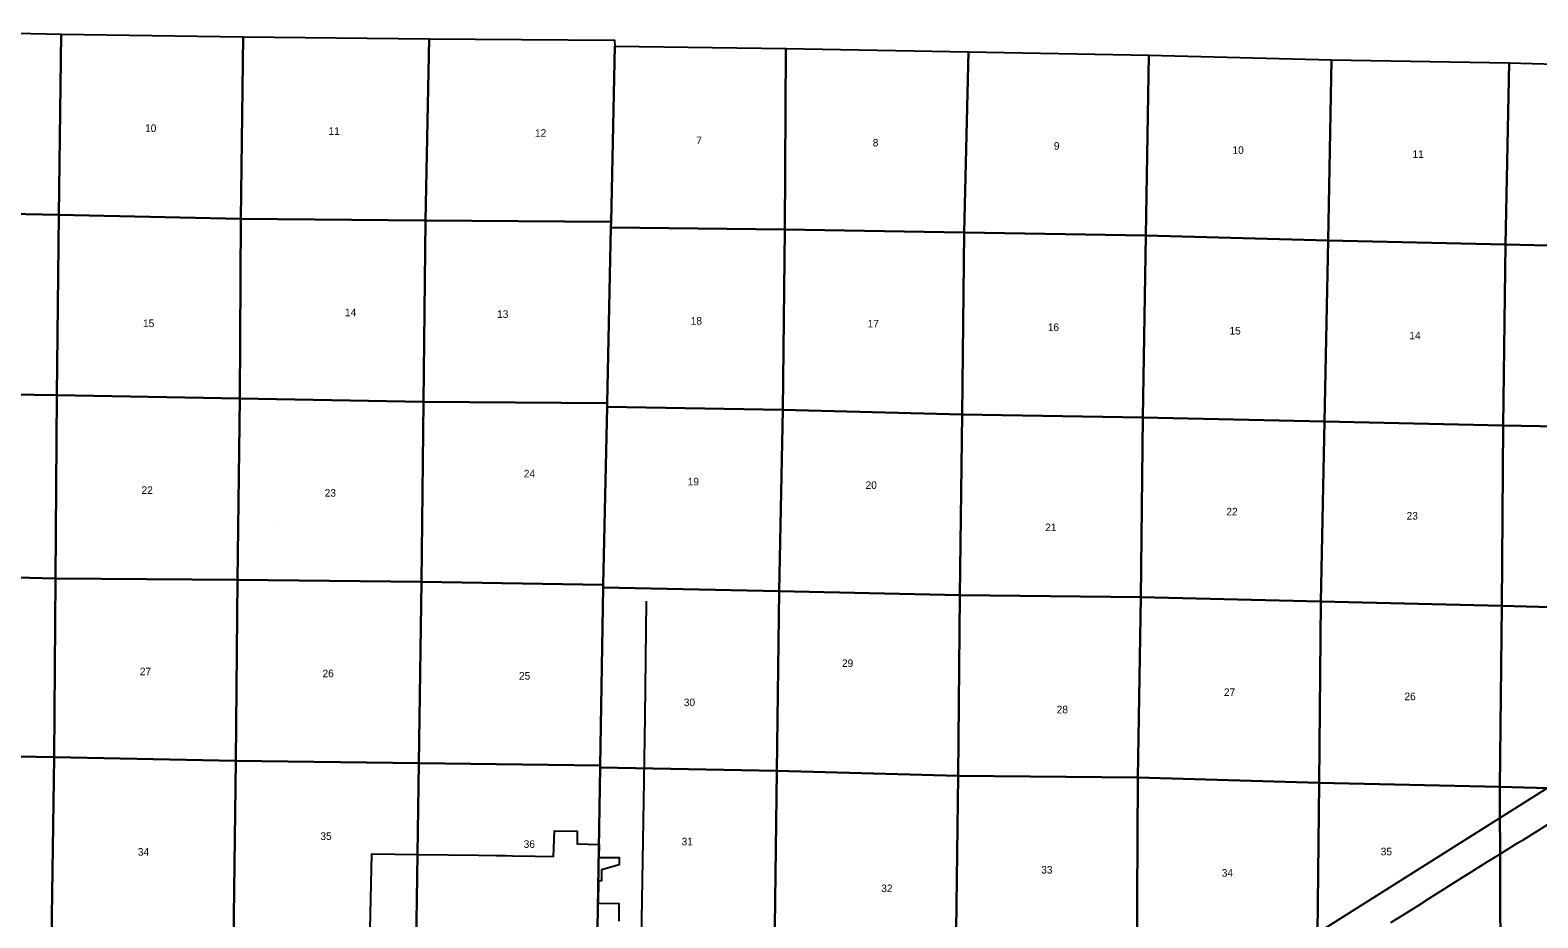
# Model space of a CAD drawing. Extents: x 1587405 to 1714697, y 1028970 to 1155083.
# Drawn here: x 1634826 to 1678758, y 1125096 to 1150963 of the extents above; entities that cross this region are included whole.
import ezdxf

# ---------------------------------------------------------------- set-up
doc = ezdxf.new("R2010")
doc.units = 0
for name, color, linetype in [('GM_X_Airport_Location_Class_3', 7, 'Continuous'), ('GM_X_Corporation', 7, 'Continuous'), ('GM_X_Interstate_Location', 7, 'Continuous'), ('GM_X_Rail_Line', 7, 'Continuous'), ('GM_X_Section', 7, 'Continuous'), ('GM_X_Section_Text', 7, 'Continuous'), ('GM_X_State_Location', 7, 'Continuous'), ('GM_X_State_Route', 7, 'Continuous'), ('GM_X_Unincorporated_Location', 7, 'Continuous')]:
    doc.layers.add(name, color=color, linetype=linetype)

msp = doc.modelspace()

# ---------------------------------------------------------------- linework, layer by layer
at = {"layer": 'GM_X_Airport_Location_Class_3'}
msp.add_line((1642071, 1136494), (1642071, 1136494), dxfattribs=at)
at = {"layer": 'GM_X_Corporation'}
msp.add_lwpolyline([(1644727, 1124331), (1644784, 1126962), (1646120, 1126944), (1647895, 1126921), (1648410, 1126912), (1648607, 1126910), (1648684, 1126908), (1648878, 1126905), (1649544, 1126894), (1650077, 1126886), (1650104, 1127635), (1650768, 1127623), (1650764, 1127251), (1651405, 1127232), (1651400, 1126856), (1651993, 1126850), (1651990, 1126644), (1651472, 1126496), (1651472, 1126171), (1651391, 1126171), (1651382, 1125527), (1651977, 1125511), (1651980, 1124997)], dxfattribs=at)
at = {"layer": 'GM_X_Rail_Line'}
for points in [[(1653568, 1112819), (1655300, 1113913), (1659870, 1116798), (1669731, 1123017), (1672359, 1124671), (1681695, 1130554), (1684437, 1132280), (1688527, 1134851), (1688807, 1135025), (1688953, 1135113), (1689087, 1135186), (1689268, 1135279), (1689470, 1135381), (1689588, 1135442), (1689734, 1135522), (1689884, 1135608), (1690363, 1135905), (1690749, 1136148), (1691070, 1136368)], [(1652548, 1112174), (1652519, 1112269), (1652498, 1112347), (1652484, 1112418), (1652474, 1112488), (1652466, 1112571), (1652461, 1112684), (1652464, 1112911), (1652505, 1115461), (1652527, 1116927), (1652548, 1118268), (1652590, 1120952), (1652612, 1122400), (1652653, 1125050), (1652715, 1129083), (1652745, 1130967), (1652787, 1134323)]]:
    msp.add_lwpolyline(points, dxfattribs=at)
at = {"layer": 'GM_X_Section'}
for points in [[(1630433, 1150963), (1635733, 1150849), (1635661, 1145583), (1630372, 1145688)], [(1635733, 1150849), (1641031, 1150772), (1640961, 1145469), (1635661, 1145583)], [(1641031, 1150772), (1646452, 1150709), (1646346, 1145412), (1640961, 1145469)], [(1646452, 1150709), (1651857, 1150670), (1651861, 1150497), (1651755, 1145373), (1646346, 1145412)], [(1651861, 1150497), (1656847, 1150430), (1656816, 1145157), (1651747, 1145211), (1651755, 1145373)], [(1656847, 1150430), (1662164, 1150328), (1662038, 1145064), (1656816, 1145157)], [(1662164, 1150328), (1667424, 1150230), (1667334, 1144976), (1662038, 1145064)], [(1667424, 1150230), (1672742, 1150098), (1672650, 1144837), (1667334, 1144976)], [(1672742, 1150098), (1677925, 1150009), (1677820, 1144716), (1672650, 1144837)], [(1677925, 1150009), (1683291, 1149852), (1683213, 1144589), (1677820, 1144716)], [(1630372, 1145688), (1635661, 1145583), (1635601, 1140326), (1630302, 1140403)], [(1635661, 1145583), (1640961, 1145469), (1640933, 1140234), (1635601, 1140326)], [(1640961, 1145469), (1646346, 1145412), (1646287, 1140136), (1640933, 1140234)], [(1646346, 1145412), (1651755, 1145373), (1651747, 1145211), (1651642, 1140090), (1646287, 1140136)], [(1651747, 1145211), (1656816, 1145157), (1656763, 1139895), (1651642, 1139982), (1651642, 1140090)], [(1662038, 1145064), (1661982, 1139762), (1656763, 1139895), (1656816, 1145157)], [(1667334, 1144976), (1667248, 1139679), (1661982, 1139762), (1662038, 1145064)], [(1672650, 1144837), (1672545, 1139561), (1667248, 1139679), (1667334, 1144976)], [(1677820, 1144716), (1677747, 1139442), (1672545, 1139561), (1672650, 1144837)], [(1683213, 1144589), (1683123, 1139347), (1677747, 1139442), (1677820, 1144716)], [(1630302, 1140403), (1635601, 1140326), (1635561, 1134983), (1630259, 1135120)], [(1635601, 1140326), (1640933, 1140234), (1640872, 1134949), (1635561, 1134983)], [(1640933, 1140234), (1646287, 1140136), (1646226, 1134889), (1640872, 1134949)], [(1646287, 1140136), (1651642, 1140090), (1651642, 1139982), (1651525, 1134804), (1646226, 1134889)], [(1651642, 1139982), (1656763, 1139895), (1656654, 1134619), (1651524, 1134718), (1651525, 1134804)], [(1656763, 1139895), (1661982, 1139762), (1661911, 1134500), (1656654, 1134619)], [(1661982, 1139762), (1667248, 1139679), (1667189, 1134440), (1661911, 1134500)], [(1667248, 1139679), (1672545, 1139561), (1672435, 1134317), (1667189, 1134440)], [(1672545, 1139561), (1677747, 1139442), (1677705, 1134187), (1672435, 1134317)], [(1677747, 1139442), (1683123, 1139347), (1683127, 1139277), (1683047, 1134044), (1677705, 1134187)], [(1635561, 1134983), (1635521, 1129774), (1630217, 1129877), (1630259, 1135120)], [(1640872, 1134949), (1640821, 1129675), (1635521, 1129774), (1635561, 1134983)], [(1646226, 1134889), (1646147, 1129603), (1640821, 1129675), (1640872, 1134949)], [(1651525, 1134804), (1651524, 1134718), (1651432, 1129536), (1646147, 1129603), (1646226, 1134889)], [(1656654, 1134619), (1656587, 1129382), (1651431, 1129478), (1651432, 1129536), (1651524, 1134718)], [(1656654, 1134619), (1661911, 1134500), (1661871, 1129233), (1656587, 1129382)], [(1661911, 1134500), (1667189, 1134440), (1667104, 1129185), (1661871, 1129233)], [(1667189, 1134440), (1672435, 1134317), (1672391, 1129030), (1667104, 1129185)], [(1672435, 1134317), (1677705, 1134187), (1677648, 1128918), (1672391, 1129030)], [(1677705, 1134187), (1683047, 1134044), (1683047, 1133992), (1682995, 1128763), (1677648, 1128918)], [(1630217, 1129877), (1635521, 1129774), (1635452, 1124488), (1635336, 1124489), (1630175, 1124565)], [(1635521, 1129774), (1640821, 1129675), (1640754, 1124394), (1635452, 1124488)], [(1640821, 1129675), (1646147, 1129603), (1646074, 1124319), (1646050, 1124319), (1640754, 1124394)], [(1646147, 1129603), (1651432, 1129536), (1651431, 1129478), (1651350, 1124201), (1646074, 1124319)], [(1651431, 1129478), (1656587, 1129382), (1656514, 1124092), (1656340, 1124096), (1651350, 1124201)], [(1656587, 1129382), (1661871, 1129233), (1661797, 1123966), (1656514, 1124092)], [(1661871, 1129233), (1667104, 1129185), (1667070, 1123870), (1661837, 1123968), (1661797, 1123966)], [(1667104, 1129185), (1672391, 1129030), (1672328, 1123761), (1667070, 1123870)], [(1672391, 1129030), (1677648, 1128918), (1677670, 1123620), (1672404, 1123756), (1672328, 1123761)], [(1677648, 1128918), (1682995, 1128763), (1682911, 1123475), (1677670, 1123620)]]:
    msp.add_lwpolyline(points, close=True, dxfattribs=at)
at = {"layer": 'GM_X_State_Route'}
msp.add_lwpolyline([(1674479, 1124959), (1674826, 1125178), (1675286, 1125466), (1675576, 1125651), (1676520, 1126248), (1676728, 1126379), (1677286, 1126725), (1677523, 1126872), (1677649, 1126950), (1678176, 1127277), (1678346, 1127383), (1679713, 1128231)], dxfattribs=at)
at = {"layer": 'GM_X_Unincorporated_Location'}
msp.add_line((1651584, 1134718), (1651584, 1134718), dxfattribs=at)

# ---------------------------------------------------------------- texts
at = {"layer": 'GM_X_Interstate_Location'}
for s in ['.', '-', ',']:
    msp.add_text(s, height=1, dxfattribs=at).set_placement((1648860, 1137098))
msp.add_text('75', height=1, rotation=0, dxfattribs=at).set_placement((1648656, 1136891))
at = {"layer": 'GM_X_Section_Text'}
for s, p in [('10', (1638175, 1147995)), ('11', (1643523, 1147912)), ('12', (1649536, 1147856)), ('7', (1654237, 1147641)), ('8', (1659378, 1147573)), ('9', (1664656, 1147480)), ('10', (1669861, 1147359)), ('11', (1675106, 1147238)), ('14', (1644000, 1142627)), ('13', (1648431, 1142579)), ('15', (1638115, 1142311)), ('18', (1654074, 1142381)), ('17', (1659229, 1142300)), ('16', (1664478, 1142196)), ('15', (1669771, 1142093)), ('14', (1675014, 1141956)), ('24', (1649210, 1137930)), ('19', (1653986, 1137697)), ('22', (1638071, 1137450)), ('23', (1643409, 1137369)), ('20', (1659169, 1137596)), ('22', (1669681, 1136821)), ('21', (1664403, 1136365)), ('23', (1674935, 1136700)), ('29', (1658481, 1132406)), ('27', (1638023, 1132164)), ('26', (1643345, 1132107)), ('25', (1649069, 1132036)), ('27', (1669611, 1131561)), ('30', (1653872, 1131264)), ('28', (1664738, 1131055)), ('26', (1674871, 1131438)), ('35', (1643283, 1127366)), ('36', (1649206, 1127135)), ('31', (1653808, 1127207)), ('34', (1637964, 1126906)), ('35', (1674180, 1126917)), ('33', (1664287, 1126387)), ('34', (1669549, 1126294)), ('32', (1659625, 1125846))]:
    msp.add_text(s, height=221, rotation=0, dxfattribs=at).set_placement(p)
at = {"layer": 'GM_X_State_Location'}
for p in [(1668764, 1147851), (1644216, 1143310)]:
    msp.add_text('613', height=1, rotation=0, dxfattribs=at).set_placement(p)
for s, p in [('s', (1669117, 1147924)), ('r', (1669117, 1147924)), ('s', (1644569, 1143383)), ('r', (1644569, 1143383))]:
    msp.add_text(s, height=1, dxfattribs=at).set_placement(p)

doc.saveas('drawing.dxf')
